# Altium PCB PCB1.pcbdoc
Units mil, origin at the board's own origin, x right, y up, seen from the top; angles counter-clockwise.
Board outline 6799.22 x 4460.63 mil, 2 copper layers (Top Layer, Bottom Layer); 35 components, 22 nets, 137 pads, 97 vias.
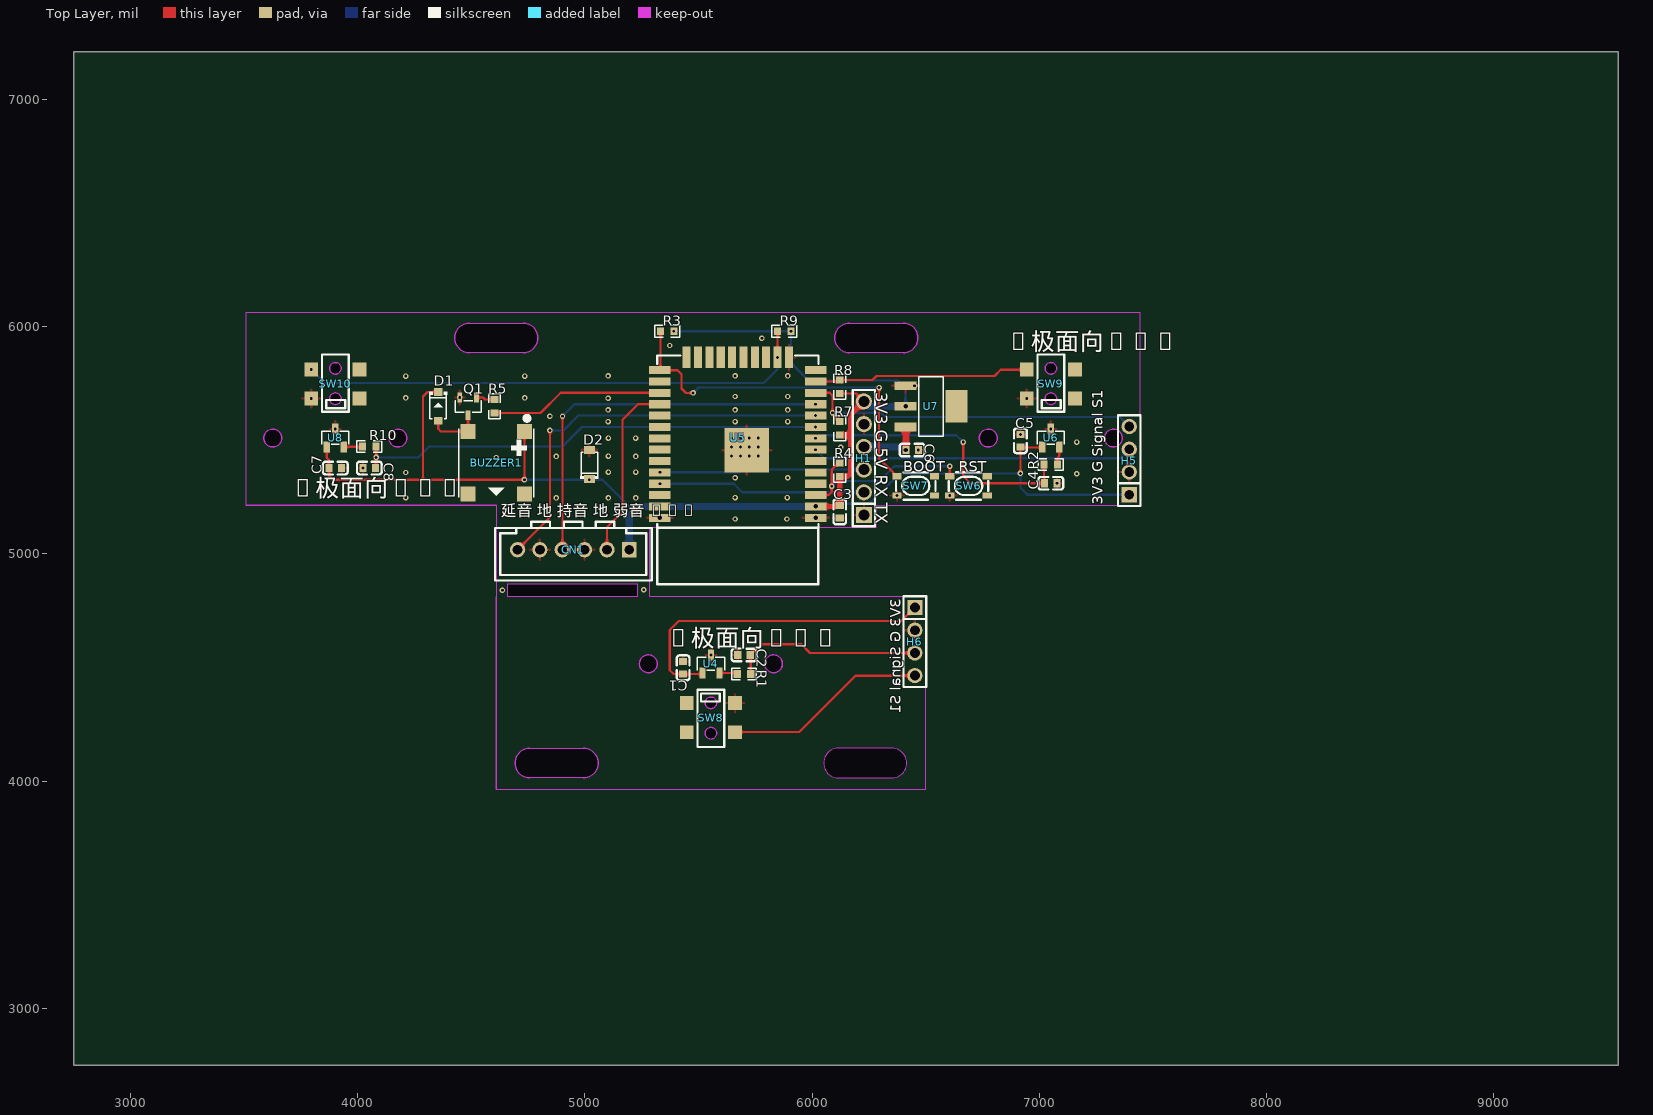
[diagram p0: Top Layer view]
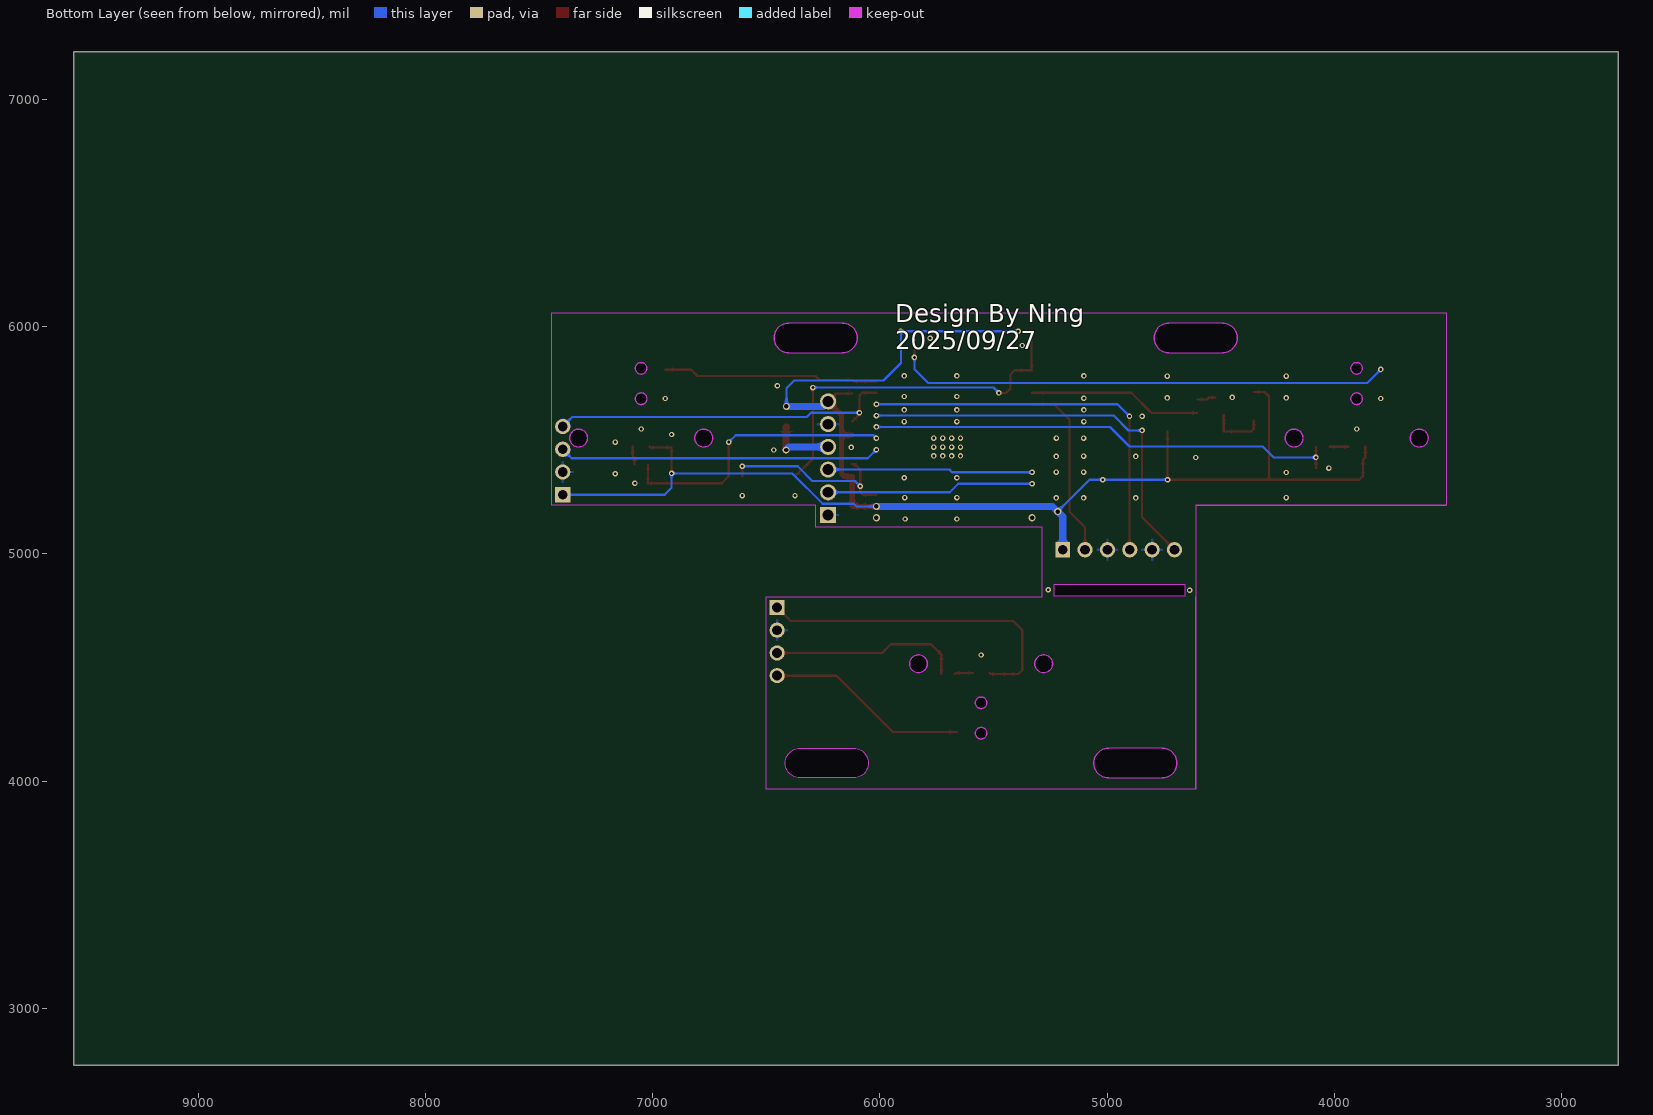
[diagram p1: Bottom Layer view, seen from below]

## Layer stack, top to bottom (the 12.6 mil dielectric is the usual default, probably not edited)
Top Layer: signal copper (thickness not stored)
Dielectric: dielectric 12.6, FR-4, Dk 4.8
Bottom Layer: signal copper (thickness not stored)

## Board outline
9549.22,2750 2750,2750 2750,7210.63 9549.22,7210.63
cut-out: 3665.35,5509.85 cw(c3625.98,5509.85) 3586.61,5509.85 cw(c3625.98,5509.85)
cut-out: 7366.14,5509.85 cw(c7326.77,5509.85) 7287.4,5509.85 cw(c7326.77,5509.85)
cut-out: 4216.54,5509.85 cw(c4177.17,5509.85) 4137.8,5509.85 cw(c4177.17,5509.85)
cut-out: 6814.96,5509.85 cw(c6775.59,5509.85) 6736.22,5509.85 cw(c6775.59,5509.85)
cut-out: 5318.9,4516.26 cw(c5279.53,4516.26) 5240.16,4516.26 cw(c5279.53,4516.26)
cut-out: 5870.08,4516.26 cw(c5830.71,4516.26) 5791.34,4516.26 cw(c5830.71,4516.26)
cut-out: 4492.13,5885.83 cw(c4492.13,5950.79) 4492.13,6015.75 4728.35,6015.75 cw(c4728.35,5950.79) 4728.35,5885.83
cut-out: 6165.35,5885.83 cw(c6165.35,5950.79) 6165.35,6015.75 6401.57,6015.75 cw(c6401.57,5950.79) 6401.57,5885.83
cut-out: 4757.6,4144.22 4993.82,4144.22 cw(c4993.82,4079.26) 4993.82,4014.3 4757.6,4014.3 cw(c4757.6,4079.26)
cut-out: 6352.09,4144.22 6115.87,4144.22 ccw(c6115.87,4079.26) 6115.87,4014.3 6352.09,4014.3 ccw(c6352.09,4079.26)
cut-out: 5233.82,4866.15 4659.53,4866.15 4659.53,4813 4659.48,4813 5233.82,4813

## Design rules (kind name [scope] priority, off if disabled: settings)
BoardOutlineClearance copperThickness1oz [All] p0: genericclearance=10 ignorepadtopadclearanceinfootprint=FALSE except(0: Arc-SplitContinuation Track-SplitContinuation SMDPad-SplitContinuation THPad-SplitContinuation Via-SplitContinuation Fill-SplitContinuation Poly-SplitContinuation Region-SplitContinuation Text-SplitContinuation; 6: Track-CutoutEdge SMDPad-CutoutEdge THPad-CutoutEdge Via-CutoutEdge Region-CutoutEdge; 11.8: Track-OutlineEdge SMDPad-OutlineEdge THPad-OutlineEdge Via-OutlineEdge Fill-OutlineEdge Region-OutlineEdge Poly-OutlineEdge Text-OutlineEdge Fill-CutoutEdge)
BoardOutlineClearance copperThickness2oz [All] p0: genericclearance=10 ignorepadtopadclearanceinfootprint=FALSE except(0: Arc-SplitContinuation Track-SplitContinuation SMDPad-SplitContinuation THPad-SplitContinuation Via-SplitContinuation Fill-SplitContinuation Poly-SplitContinuation Region-SplitContinuation Text-SplitContinuation; 6: Track-CutoutEdge SMDPad-CutoutEdge THPad-CutoutEdge Via-CutoutEdge Region-CutoutEdge; 11.8: Track-OutlineEdge SMDPad-OutlineEdge THPad-OutlineEdge Via-OutlineEdge Fill-OutlineEdge Region-OutlineEdge Poly-OutlineEdge Text-OutlineEdge Fill-CutoutEdge)
Clearance copperThickness1oz [(InNet('3V3') OR InNet('$1N2451') OR InNet('GND') OR InNet('SIGNAL1') OR InNet('5V') OR InNet('$1N2441') OR InNet('$1N652') OR InNet('$1N2297') OR InNet('IO0') OR InNet('EN') OR InNet('SPEAKER') OR InNet('OUT3') OR InNet('S1') OR InNet('S2') OR InNet('S3') OR InNet('SIGNAL2') OR InNet('DOUT1') OR InNet('DOUT2') OR InNet('RXD') OR InNet('TXD') OR InNet('SIGNAL3') OR InNet('$1N5432'))] p1: gap=7 ignorepadtopadclearanceinfootprint=FALSE except(4: Track-Track; 6: Track-SMDPad SMDPad-SMDPad Track-THPad SMDPad-THPad THPad-THPad Track-Via SMDPad-Via THPad-Via Via-Via SMDPad-Fill THPad-Fill Via-Fill Fill-Fill Track-Region SMDPad-Region THPad-Region Via-Region Region-Region Track-Poly SMDPad-Poly THPad-Poly Via-Poly Fill-Poly Region-Poly Poly-Poly Track-Text SMDPad-Text THPad-Text Via-Text Fill-Text Region-Text Poly-Text Text-Text; 6.9: Track-Hole SMDPad-Hole THPad-Hole Via-Hole Fill-Hole Region-Hole Poly-Hole Text-Hole Sheet-Hole; 11.8: Track-Fill Fill-Region Track-Sheet SMDPad-Sheet THPad-Sheet Via-Sheet Fill-Sheet Region-Sheet Poly-Sheet Text-Sheet)
Clearance copperThickness2oz [All] p1: gap=7 ignorepadtopadclearanceinfootprint=FALSE except(6: Track-SMDPad SMDPad-SMDPad Track-THPad SMDPad-THPad THPad-THPad Track-Via SMDPad-Via THPad-Via Via-Via SMDPad-Fill THPad-Fill Via-Fill Fill-Fill Track-Region SMDPad-Region THPad-Region Via-Region Region-Region Track-Poly SMDPad-Poly THPad-Poly Via-Poly Fill-Poly Region-Poly Poly-Poly Track-Text SMDPad-Text THPad-Text Via-Text Fill-Text Region-Text Poly-Text Text-Text; 6.9: Track-Hole SMDPad-Hole THPad-Hole Via-Hole Fill-Hole Region-Hole Poly-Hole Text-Hole Sheet-Hole; 8: Track-Track; 11.8: Track-Fill Fill-Region Track-Sheet SMDPad-Sheet THPad-Sheet Via-Sheet Fill-Sheet Region-Sheet Poly-Sheet Text-Sheet)
DiffPairsRouting differentialPair [All] p1: maxuncoupledlength=10 minlimit=6 maxlimit=6 mostfreqgap=6 toplayer_minwidth=5 toplayer_prefwidth=10 toplayer_maxwidth=100 bottomlayer_minwidth=5 bottomlayer_prefwidth=10 bottomlayer_maxwidth=100
PasteMaskExpansion pasteMaskExpansion [All] p1: expansion=0
PlaneConnect innerPlane [All] p1: planeconnectstyle=Relief reliefexpansion=20 reliefentries=4 reliefconductorwidth=10 reliefairgap=10
PolygonConnect copperRegion [All] p1: connectstyle=Relief reliefentries=4 reliefconductorwidth=10 polygonreliefangle="90 Angle" airgapwidth=10
RoutingVias viaSize [All] p1: viastyle="Through Hole" holewidth=12.0078 minholewidth=11.811 maxholewidth=248.0314 width=24.0158 minwidth=19.685 maxwidth=393.7008
SolderMaskExpansion solderMaskExpansion [All] p1: useseparateexpansions=TRUE expansion=2 expansionbottom=2
Width copperThickness1oz [All] p1: maxlimit=100 minlimit=5 preferedwidth=10
Width copperThickness2oz [All] p1: maxlimit=100 minlimit=8 preferedwidth=10

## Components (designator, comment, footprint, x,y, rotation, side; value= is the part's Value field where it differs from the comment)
BUZZER1 "MLT-7525" BUZ-SMD_4P-L7.5-W7.5-P7.59-TL 4610.24,5401.58 r270 top locked
C1 "CC0603KRX7R9BB103" C0603 5432.8,4498.55 r90 top
C2 "CC0603JRNPO9BN152" C0603 5700.79,4555.12 r180 top locked
C3 "CL10A106MA8NRNC" C0603 6122.05,5185.04 r270 top
C4 "CC0603JRNPO9BN152" C0603 7051.18,5311.03 r0 top
C5 "CC0603KRX7R9BB103" C0603 6917.32,5498.03 r90 top
C6 "CL10A106MA8NRNC" C0603 6440.66,5457.32 r180 top
C7 "CC0603KRX7R9BB103" C0603 3901.57,5377.96 r0 top
C8 "CC0603JRNPO9BN152" C0603 4051.28,5377.96 r180 top
CN1 "HC-XHB-6A" CONN-TH_6P-P2.50_HCTL_HC-XHB-6A 4949.54,5018.22 r180 top locked
D1 "1N4148W_C7420318" SOD-123_L2.7-W1.6-LS3.7-FD 4354.33,5649.61 r90 top locked
D2 "BZT52C3V3_C19077396" SOD-123_L2.7-W1.6-LS3.7-RD 5019.68,5393.7 r90 top locked
H1 "2.54-1x6P直针" HDR-TH_6P-P2.54-V-M-1 6228.35,5421.26 r90 top locked
H5 "PZ254V-11-04P" HDR-TH_4P-P2.54-V-M 7396.46,5410.63 r90 top locked
H6 "PZ254V-11-04P" HDR-TH_4P-P2.54-V-M 6452.76,4614.18 r270 top locked
Q1 "S8050_C20069125" SOT-23-3_L2.9-W1.3-P1.90-LS2.3-BR 4486.22,5649.61 r90 top locked
R1 "0603WAF1002T5E" R0603 5700.51,4470.99 r180 top locked
R2 "0603WAF1002T5E" R0603 7051.18,5393.7 r0 top
R3 "0603WAF1002T5E" R0603 5362.2,5980.32 r0 top locked
R4 "0603WAF1002T5E" R0603 6122.05,5370.23 r270 top
R5 "0603WAF1800T5E" R0603 4602.36,5649.61 r90 top locked
R7 "0603WAF1002T5E" R0603 6122.05,5553.23 r90 top
R8 "0603WAF1002T5E" R0603 6122.05,5736.22 r90 top
R9 "0603WAF1002T5E" R0603 5877.95,5980.32 r180 top locked
R10 "0603WAF1002T5E" R0603 4051.18,5472.44 r180 top locked
SW6 "SKRPACE010" KEY-SMD_4P-L4.2-W3.2-P2.20-LS4.6 6688.98,5299.22 r0 top
SW7 "SKRPACE010" KEY-SMD_4P-L4.2-W3.2-P2.20-LS4.6 6456.69,5299.22 r0 top
SW8 "TM-T07A-6" SW-SMD_TM-T07A-4 5554.84,4279.53 r90 top locked
SW9 "TM-T07A-6" SW-SMD_TM-T07A-4 7051.18,5748.04 r270 top locked
SW10 "TM-T07A-6" SW-SMD_TM-T07A-4 3901.57,5748.04 r270 top locked
U4 "DRV5053VAQDBZR" SOT-23-3_L2.9-W1.3-P1.90-LS2.4-BR 5554.84,4515.57 r270 top locked
U5 "ESP32-WROOM-32-N8" WIFIM-SMD_39P-L25.5-W18.0-P1.27 5673.23,5511.81 r180 top locked
U6 "DRV5053VAQDBZR" SOT-23-3_L2.9-W1.3-P1.90-LS2.4-BR 7051.18,5510.54 r270 top locked
U7 "AMS1117-3.3_C347222" SOT-223-4_L6.5-W3.5-P2.30-LS7.0-BR 6523.62,5649.61 r180 top
U8 "DRV5053VAQDBZR" SOT-23-3_L2.9-W1.3-P1.90-LS2.4-BR 3901.57,5510.54 r270 top locked

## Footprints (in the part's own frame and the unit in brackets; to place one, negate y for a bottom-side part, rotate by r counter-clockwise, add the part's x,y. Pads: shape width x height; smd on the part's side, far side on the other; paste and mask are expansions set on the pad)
BUZ-SMD_4P-L7.5-W7.5-P7.59-TL [mm]
  rect 1.681x1.68 smd: 1(-3.497,3.15) 2(-3.497,-3.15) 3(3.497,-3.15) 4(3.497,3.15)
  silkscreen extent -5.2,-4.19 3.84,4.19
C0603 [mm]
  rect 0.8x0.9 smd: 1(-0.7,0) 2(0.7,0)
  silkscreen extent -1.39,-0.71 1.39,0.71
CONN-TH_6P-P2.50_HCTL_HC-XHB-6A [mm]
  rect 1.6x1.7 hole 1.1: 1(-6.25,0)
  round 1.7 hole 1.1: 2(-3.75,0) 3(-1.25,0) 4(1.25,0) 5(3.75,0) 6(6.25,0)
  silkscreen extent -8.75,-3.14 8.76,3.44
HDR-TH_4P-P2.54-V-M [mm]
  rect 1.7x1.7 hole 1.1: 1(-3.81,0)
  round 1.7 hole 1.1: 2(-1.27,0) 3(1.27,0) 4(3.81,0)
  silkscreen extent -5.08,-1.27 5.08,1.27
HDR-TH_6P-P2.54-V-M-1 [mm]
  rect 1.8x1.8 hole 1.2: 1(-6.35,0)
  round 1.8 hole 1.2: 2(-3.81,0) 3(-1.27,0) 4(1.27,0) 5(3.81,0) 6(6.35,0)
  silkscreen extent -7.62,-1.25 7.62,1.25
KEY-SMD_4P-L4.2-W3.2-P2.20-LS4.6 [mm]
  rect 1.05x0.7 smd: 1(-2.1,1.075) 2(2.1,1.075) 3(-2.1,-1.075) 4(2.1,-1.075)
  silkscreen extent -2.2,-1.55 2.2,1.52
R0603 [mil]
  rect 31.75x34.02 smd: 1(-29.66,0) 2(29.66,0)
  silkscreen extent -55,-26 55,26
SOD-123_L2.7-W1.6-LS3.7-FD [mm]
  rect 0.88x0.96 smd: 1(-1.61,0) 2(1.61,0)
  silkscreen extent -1.38,-1 1.6,1
SOD-123_L2.7-W1.6-LS3.7-RD [mm]
  rect 0.91x1.22 smd: 1(-1.635,0) 2(1.635,0)
  silkscreen extent -1.6,-1 1.38,1
SOT-23-3_L2.9-W1.3-P1.90-LS2.3-BR [mm]
  rect 1.07x0.532 smd: 1(0.99,-0.95) 2(0.99,0.95) 3(-0.99,0)
  silkscreen extent -0.66,-1.45 0.64,1.45
SOT-23-3_L2.9-W1.3-P1.90-LS2.4-BR [mm]
  rect 1.25x0.7 smd: 1(1,-0.95) 2(1,0.95) 3(-1,0)
  silkscreen extent -0.73,-1.53 0.73,1.53
SOT-223-4_L6.5-W3.5-P2.30-LS7.0-BR [mm]
  rect 2.47x0.98 smd: 1(2.835,-2.3) 2(2.835,0) 3(2.835,2.3)
  rect 2.47x3.6 smd: 4(-2.835,0)
  silkscreen extent -1.37,-3.33 1.37,3.33
SW-SMD_TM-T07A-4 [mil]
  rect 60x60 smd: 1(-63.97,-106.3) 2(63.98,-106.3) 3(63.98,106.3) 4(-63.97,106.3)
  Board Outline Layer circle w1: c64.96,0 r25.59
  Board Outline Layer circle w1: c-68.9,0.2 r25.59
  Board Outline Layer region: 64.96,-25.59 53.86,-23.06 44.95,-15.96 40.01,-5.69 40.01,5.69 44.95,15.96 53.86,23.06 64.96,25.59 64.96,25.59 76.06,23.06 84.97,15.96 89.91,5.69 89.91,-5.69 84.97,-15.96 76.06,-23.06 64.96,-25.59
  Board Outline Layer region: -68.9,-25.39 -80,-22.86 -88.91,-15.76 -93.85,-5.5 -93.85,5.89 -88.91,16.15 -80,23.25 -68.9,25.79 -68.9,25.79 -57.79,23.25 -48.89,16.15 -43.95,5.89 -43.95,-5.5 -48.89,-15.76 -57.79,-22.86 -68.9,-25.39
  Multi-Layer board cut-out: 64.96,-25.59 53.86,-23.06 44.95,-15.96 40.01,-5.69 40.01,5.69 44.95,15.96 53.86,23.06 64.96,25.59 64.96,25.59 76.06,23.06 84.97,15.96 89.91,5.69 89.91,-5.69 84.97,-15.96 76.06,-23.06 64.96,-25.59
  Multi-Layer board cut-out: -68.9,-25.39 -80,-22.86 -88.91,-15.76 -93.85,-5.5 -93.85,5.89 -88.91,16.15 -80,23.25 -68.9,25.79 -68.9,25.79 -57.79,23.25 -48.89,16.15 -43.95,5.89 -43.95,-5.5 -48.89,-15.76 -57.79,-22.86 -68.9,-25.39
  silkscreen extent -130,-59 122,59
WIFIM-SMD_39P-L25.5-W18.0-P1.27 [mm]
  rect 2.4x0.9 smd: 1(-8.7,8.965) 2(-8.7,7.695) 3(-8.7,6.425) 4(-8.7,5.155) 5(-8.7,3.885) 6(-8.7,2.615) 7(-8.7,1.345) 8(-8.7,0.075) 9(-8.7,-1.195) 10(-8.7,-2.465) 11(-8.7,-3.735) 12(-8.7,-5.005) 13(-8.7,-6.275) 14(-8.7,-7.545) 25(8.7,-7.545) 26(8.7,-6.275) 27(8.7,-5.005) 28(8.7,-3.735) 29(8.7,-2.465) 30(8.7,-1.195) 31(8.7,0.075) 32(8.7,1.345) 33(8.7,2.615) 34(8.7,3.885) 35(8.7,5.155) 36(8.7,6.425) 37(8.7,7.695) 38(8.7,8.965)
  rect 0.9x2.4 smd: 15(-5.715,-8.965) 16(-4.445,-8.965) 17(-3.175,-8.965) 18(-1.905,-8.965) 19(-0.635,-8.965) 20(0.635,-8.965) 21(1.905,-8.965) 22(3.175,-8.965) 23(4.445,-8.965) 24(5.715,-8.965)
  rect 5x5 smd: 39(-1.017,1.422)
  silkscreen extent -9.02,-9.17 9.02,16.39

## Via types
v1: diameter 24.02, hole 12.01, Top Layer to Bottom Layer, 91 vias
v2: diameter 31.5, hole 19.68, Top Layer to Bottom Layer, 6 vias

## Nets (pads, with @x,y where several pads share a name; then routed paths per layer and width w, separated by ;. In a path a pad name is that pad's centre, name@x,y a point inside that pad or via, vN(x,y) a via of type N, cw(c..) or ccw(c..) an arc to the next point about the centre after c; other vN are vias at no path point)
3V3: BUZZER1.1 C1.1 C3.1 C5.1 C7.1 CN1.1 D1.2 D2.1 H1.6 H5.1 H6.1 R3.2 R4.2 R7.1 R8.1 R9.1 U4.1 U5.2 U6.1 U7.2 U8.1 | length 8637.7
  Top Layer w10: U8.1 3864.17,5423.23 3874.01,5413.39 C7.1 3874.01,5342.52 3889.76,5326.78 4286.9,5326.78 ; D1.2 4307.48,5713 4287.4,5692.92 4287.4,5327.27 4286.9,5326.78 ; BUZZER1.1 v1(4734.25,5326.78) 4286.9,5326.78 ; U4.1 5512.23,4470.99 C1.1 5391.22,4470.99 5374.02,4488.19 5374.02,4665.36 5413.39,4704.73 6393.31,4704.73 H6.1 ; R8.1 6193.05,5706.56 H1.6 ; v1(6917.32,5354.33) C5.1@6917.32,5468.51 ; C5.1 C5.1@6917.32,5468.51 ; U6.1 7011.12,5468.51 C5.1@6917.32,5468.51
  Top Layer w23.62: v2(6015.74,5208.86) 6118.3,5208.86 C3.1 R4.2 6155.53,5340.57 6169.29,5354.33 6169.29,5525.61 ; R7.1 6167.25,5523.57 6169.29,5525.61 ; H1.6 6169.29,5612.21 6169.29,5525.61
  Bottom Layer w10: v1@4732.28,5326.78 v1(5019.46,5326.78) 5077.27,5326.78 v2(5217.77,5186.28) ; v1@5393.7,5980.32 v1(5907.61,5980.32) 5907.61,5840.42 5984.25,5763.78 6377.95,5763.78 6412.01,5729.72 v2(6412.01,5649.61) ; v2(6015.74,5208.86) 6102.56,5208.86 6114.17,5220.48 6251.97,5220.48 6385.83,5354.33 v1(6917.32,5354.33) 6917.32,5291.34 6948.03,5260.63 H5.1
  Bottom Layer w31.5: CN1.1 5195.61,5164.12 v2(5217.77,5186.28) 5240.16,5208.67 v2@6015.74,5208.67 ; H1.6 6250,5649.61 v2(6412.01,5649.61)
  other v1: 5391.86,5980.32
5V: C6.2 H1.4 U7.3 | length 292.7
  Top Layer w31.5: U7.3 6413.1,5557.97 v2(6413.1,5457.32)
  Bottom Layer w31.5: H1.4 6399.16,5471.26 v2(6413.1,5457.32)
$1N652: R1.2 U4.2 | length 80.8
  Top Layer w10: U4.2 5665.64,4476.2 R1.2
$1N2297: R2.2 U6.2 | length 80.7
  Top Layer w10: R2.2 7080.84,5423.36 7088.58,5431.1 U6.2
$1N2441: Q1.1 R5.2 | length 82.6
  Top Layer w10: Q1.1 4551.57,5688.6 4560.89,5679.27 R5.2
$1N2451: BUZZER1.2 D1.1 Q1.3 | length 243.2
  Top Layer w10: D1.1 4354.33,5551.19 4366.24,5539.27 BUZZER1.2 Q1.3
$1N5432: R10.2 U8.2 | length 83.1
  Top Layer w10: U8.2 4020.24,5471.17 R10.2
DOUT1: CN1.6 U5.10 | length 1780.8
  Top Layer w10: CN1.6 4846.46,5161.2 v1(4846.46,5543.31)
  Bottom Layer w10: v1(4846.46,5543.31) 4905.51,5543.31 4971.06,5608.86 v1(6015.74,5608.86)
DOUT2: CN1.4 U5.11 | length 1724.5
  Top Layer w10: CN1.4 4901.57,5019.46 v1(4901.57,5606.3)
  Bottom Layer w10: v1(4901.57,5606.3) 4954.13,5658.86 v1(6015.74,5658.86)
EN: R4.1 SW6.1 U5.3 | length 821.4
  Top Layer w10: U5.3 6073.82,5258.86 6086.61,5271.66 v1(6086.61,5297.41) 6086.61,5371.02 6110.24,5394.64 R4.1@6122.05,5394.64 ; SW6.1 v1(6606.3,5385.83)
  Bottom Layer w10: v1(6086.61,5297.41) 6110.47,5321.26 6297.64,5321.26 6362.21,5385.83 v1(6606.3,5385.83)
GND: C1.2 C2.2 C3.2 C4.2 C5.2 C6.1 C7.2 C8.2 CN1.3 CN1.5 D2.2 H1.1 H1.5 H5.2 H6.2 Q1.2 SW6.3 SW7.3 SW8.2 SW9.2 SW10.2 U4.3 U5.1 U5.15 U5.38 U5.39 U6.3 U7.1 U8.3
  other v1: 5554.84,4554.94 4637.4,4839.57 5259.84,4842.52 5661.42,5153.55 5889.76,5153.55 4874.02,5246.18 5103.82,5246.18 5224.41,5246.18 4211.81,5248.04 5661.42,5248.04 5891.56,5248.04 6374.01,5256.9 6606.3,5256.9 7078.74,5311.03 5661.42,5334.65 5893.69,5334.65 7165.36,5352.69 4211.81,5358.32 5103.82,5360.13 5224.41,5360.13 4023.72,5377.96 4610.24,5424.34 4874.02,5429.14 5224.41,5429.14 5103.82,5430.67 5645.56,5431.11 5684.93,5431.11 5724.3,5431.11 5763.67,5431.11 6468.22,5457.32 6125.98,5468.51 5645.56,5470.48 5684.93,5470.48 5724.3,5470.48 5763.67,5470.48 7165.36,5492.13 5103.82,5509.85 5223.2,5509.85 5645.56,5509.85 5684.93,5509.85 5724.3,5509.85 5763.67,5509.85 6917.32,5525.59 3901.57,5549.91 7051.18,5549.91 5102.36,5582.6 5661.42,5582.68 5893.69,5582.68 4846.46,5606.3 5102.36,5633.86 5661.42,5633.86 5892.79,5633.86 3795.27,5684.06 6944.88,5684.06 5102.36,5685.04 4211.81,5686.62 4735.39,5686.6 4448.82,5688.6 5661.42,5692.92 5892.79,5692.92 6451.38,5740.16 4211.81,5782.91 4735.39,5782.91 5102.36,5783.47 5661.42,5783.47 5892.79,5783.47 5374.02,5917.33 5779.53,5948.82
  other v2: 5330.71,5158.86 6015.74,5158.86
IO0: R3.1 SW7.1 U5.25 | length 1648.3
  Top Layer w10: R3.1 5332.54,5810.69 U5.25 5407.68,5808.86 5425.2,5791.34 5425.2,5728.35 5444.88,5708.67 v1(5476.38,5708.67) ; v1(6295.28,5732.29) 6295.28,5420.27 SW7.1
  Bottom Layer w10: v1(5476.38,5708.67) 5500,5732.29 v1(6295.28,5732.29)
OUT3: CN1.2 U5.28 | length 794.2
  Top Layer w10: CN1.2 5097.18,5116.87 5165.35,5185.04 5165.35,5590.56 5233.66,5658.86 U5.28
RXD: H1.3 U5.34 | length 902.8
  Bottom Layer w10: v1(5330.71,5358.86) 5681.69,5358.86 5694.09,5371.26 H1.3
S1: H5.4 H6.4 R7.2 SW8.1 U5.12 | length 2432.5
  Top Layer w10: SW8.1 5943.9,4215.56 6192.52,4464.18 H6.4 ; U5.12 6078.55,5708.86 6090.55,5696.85 v1(6090.55,5621.51) 6090.55,5614.38 R7.2
  Bottom Layer w10: v1(6090.55,5621.51) 6303.69,5621.51 6322.84,5602.37 7354.73,5602.37 H5.4
S2: R8.2 SW9.1 U5.13 | length 951.2
  Top Layer w10: U5.13 6115.02,5758.86 R8.2 6265.88,5765.88 6283.47,5783.47 6803.15,5783.47 6830.71,5811.03 6943.9,5811.03 SW9.1
S3: R9.2 SW10.1 U5.16 | length 2270.5
  Top Layer w10: U5.16@5848.29,5864.84 R9.2
  Bottom Layer w10: v1(3795.27,5812.01) 3855.31,5751.97 5787.4,5751.97 5848.23,5812.8 v1(5848.23,5864.77)
SIGNAL1: C2.1 H5.3 H6.3 R1.1 U5.7 | length 2257.3
  Top Layer w10: R1.1 5730.17,4553.3 C2.1 5775.59,4602.37 5952.76,4602.37 5990.95,4564.18 H6.3
  Bottom Layer w10: v1(6015.74,5458.86) 6053.34,5421.26 7357.09,5421.26 H5.3
SIGNAL2: C4.1 R2.1 U5.8 | length 1272.6
  Top Layer w10: v1(6665.35,5492.13) 6665.35,5342.52 6696.85,5311.03 C4.1 7021.52,5313.13 R2.1
  Bottom Layer w10: v1(6015.74,5508.86) 6029.72,5522.84 6634.65,5522.84 v1(6665.35,5492.13)
SIGNAL3: C8.1 R10.1 U5.9 | length 2085.8
  Top Layer w10: C8.1 4080.84,5379.96 v1(4080.84,5424.65) R10.1
  Bottom Layer w10: v1(4080.84,5424.65) 4267.16,5424.65 4314.96,5472.44 4901.57,5472.44 4987.99,5558.86 v1(6015.74,5558.86)
SPEAKER: R5.1 U5.27 | length 765.2
  Top Layer w10: R5.1 4804.99,5619.95 4893.89,5708.86 U5.27
TXD: H1.2 U5.35 | length 913.2
  Bottom Layer w10: v1(5330.71,5308.86) 5655.71,5308.86 5693.31,5271.26 H1.2
pads on no net: BUZZER1.3 BUZZER1.4 SW6.2 SW6.4 SW7.2 SW7.4 SW8.3 SW8.4 SW9.3 SW9.4 SW10.3 SW10.4 U5.4 U5.5 U5.6 U5.14 U5.17 U5.18 U5.19 U5.20 U5.21 U5.22 U5.23 U5.24 U5.26 U5.29 U5.30 U5.31 U5.32 U5.33 U5.36 U5.37 U7.4

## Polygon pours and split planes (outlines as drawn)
GND on Top Layer (solid, remove dead copper, pour order 0): 3000,6960.63 9299.22,6960.63 9299.22,3000 3000,3000
GND on Bottom Layer (solid, remove dead copper, pour order 2): 3055.12,6913.39 7937.01,6913.39 7937.01,3047.25 3055.12,3047.25

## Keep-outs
Board Outline Layer:
  circle w1: c3625.98,5509.85 r39.37
  region: 3665.35,5509.85 cw(c3625.98,5509.85) 3586.61,5509.85 cw(c3625.98,5509.85)
  circle w1: c7326.77,5509.85 r39.37
  region: 7366.14,5509.85 cw(c7326.77,5509.85) 7287.4,5509.85 cw(c7326.77,5509.85)
  circle w1: c4177.17,5509.85 r39.37
  region: 4216.54,5509.85 cw(c4177.17,5509.85) 4137.8,5509.85 cw(c4177.17,5509.85)
  circle w1: c6775.59,5509.85 r39.37
  region: 6814.96,5509.85 cw(c6775.59,5509.85) 6736.22,5509.85 cw(c6775.59,5509.85)
  circle w1: c5279.53,4516.26 r39.37
  region: 5318.9,4516.26 cw(c5279.53,4516.26) 5240.16,4516.26 cw(c5279.53,4516.26)
  circle w1: c5830.71,4516.26 r39.37
  region: 5870.08,4516.26 cw(c5830.71,4516.26) 5791.34,4516.26 cw(c5830.71,4516.26)
  region: 4492.13,5885.83 cw(c4492.13,5950.79) 4492.13,6015.75 4728.35,6015.75 cw(c4728.35,5950.79) 4728.35,5885.83
  region: 6165.35,5885.83 cw(c6165.35,5950.79) 6165.35,6015.75 6401.57,6015.75 cw(c6401.57,5950.79) 6401.57,5885.83
  region: 4757.6,4144.22 4993.82,4144.22 cw(c4993.82,4079.26) 4993.82,4014.3 4757.6,4014.3 cw(c4757.6,4079.26)
  region: 6352.09,4144.22 6115.87,4144.22 ccw(c6115.87,4079.26) 6115.87,4014.3 6352.09,4014.3 ccw(c6352.09,4079.26)
  region: 5233.82,4866.15 4659.53,4866.15 4659.53,4813 4659.48,4813 5233.82,4813
  lines w1: 4492.13,5885.83 cw(c4492.13,5950.79) 4492.13,6015.75 4728.35,6015.75 cw(c4728.35,5950.79) 4728.35,5885.83 4492.13,5885.83 ; 4659.48,4813 4659.53,4813 4659.53,4866.15 5233.82,4866.15 5233.82,4813 4659.48,4813 ; 4757.6,4014.3 4993.82,4014.3 ccw(c4993.82,4079.26) 4993.82,4144.22 4757.6,4144.22 ccw(c4757.6,4079.26) 4757.6,4014.3 ; 6115.87,4014.3 cw(c6115.87,4079.26) 6115.87,4144.22 6352.09,4144.22 cw(c6352.09,4079.26) 6352.09,4014.3 6115.87,4014.3 ; 6165.35,5885.83 cw(c6165.35,5950.79) 6165.35,6015.75 6401.57,6015.75 cw(c6401.57,5950.79) 6401.57,5885.83 6165.35,5885.83
  lines w3.94: 4610.19,4806.78 4610.2,5214.57 ; 3507.87,5214.57 3507.87,6061.03 7444.88,6061.03 7444.88,5214.57 7444.86,5214.57 6283.47,5214.57 6283.47,5118.11 5286.33,5118.11 5286.33,4813.14 5285.88,4811.54 6499.72,4811.54 6499.72,3965.08 4610.2,3965.08 ; 3507.87,5214.57 4610.2,5214.57 ; 3507.87,5214.57 4610.2,5214.57 ; 3507.87,5214.57 4610.2,5214.57 ; 4610.2,3965.08 4610.2,4811.54 ; 4610.2,3965.08 4610.2,4811.54 ; 4610.2,3965.08 4610.2,4811.54

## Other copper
Top Layer:
  region net 3V3: 4739.25,5501.18 4729.25,5501.18 ccw(c4724.25,5501.18) 4724.25,5506.18 4744.25,5506.18 ccw(c4744.25,5501.18)
  region net $1N2451: 4448.15,5534.27 4448.15,5544.27 ccw(c4448.15,5549.27) 4453.15,5549.27 4453.15,5529.27 ccw(c4448.15,5529.27)
  region net $1N2451: 4481.22,5577.36 4491.22,5577.36 ccw(c4496.22,5577.36) 4496.22,5572.36 4476.22,5572.36 ccw(c4476.22,5577.36)
  region net SIGNAL1: 5738.99,4572.84 5744.1,4563.8 5744.1,4556.73 5731.92,4572.84
  region net SIGNAL1: 5735.17,4532.4 5725.17,4532.4 ccw(c5720.17,4532.4) 5720.17,4537.4 5740.17,4537.4 ccw(c5740.17,4532.4)
  region net SIGNAL2: 7002.87,5306.03 7002.87,5316.03 ccw(c7002.87,5321.03) 7007.87,5321.03 7007.87,5301.03 ccw(c7002.87,5301.03)
  region net SIGNAL2: 7016.52,5333.74 7026.52,5333.74 ccw(c7031.52,5333.74) 7031.52,5328.74 7011.52,5328.74 ccw(c7011.52,5333.74)
  region net $1N2451: 4359.33,5563.9 4349.33,5563.9 ccw(c4344.33,5563.9) 4344.33,5568.9 4364.33,5568.9 ccw(c4364.33,5563.9)
  region net 3V3: 4330.43,5708 4330.43,5718 ccw(c4330.43,5723) 4335.43,5723 4335.43,5703 ccw(c4330.43,5703)
  region net $1N2451: 4491.22,5584.56 4481.22,5584.56 ccw(c4476.22,5584.56) 4476.22,5589.56 4496.22,5589.56 ccw(c4496.22,5584.56)
  region net $1N2441: 4539.09,5693.6 4539.09,5683.6 ccw(c4539.09,5678.6) 4534.09,5678.6 4534.09,5698.6 ccw(c4539.09,5698.6)
  region net 3V3: 5498.66,4465.99 5498.66,4475.99 ccw(c5498.66,4480.99) 5503.66,4480.99 5503.66,4460.99 ccw(c5498.66,4460.99)
  region net $1N652: 5611.02,4481.2 5611.02,4471.2 ccw(c5611.02,4466.2) 5606.02,4466.2 5606.02,4486.2 ccw(c5611.02,4486.2)
  region net 3V3: 6074.8,5220.67 6074.8,5197.05 ccw(c6074.8,5182.28) 6062.99,5191.14 6062.99,5226.57 ccw(c6074.8,5235.43)
  region net EN: 6067.99,5263.86 6067.99,5253.86 ccw(c6067.99,5248.86) 6062.99,5248.86 6062.99,5268.86 ccw(c6067.99,5268.86)
  region net S1: 6067.99,5713.86 6067.99,5703.86 ccw(c6067.99,5698.86) 6062.99,5698.86 6062.99,5718.86 ccw(c6067.99,5718.86)
  region net S2: 6067.99,5763.86 6067.99,5753.86 ccw(c6067.99,5748.86) 6062.99,5748.86 6062.99,5768.86 ccw(c6067.99,5768.86)
  region net S3: 5843.29,5917.02 5853.29,5917.02 ccw(c5858.29,5917.02) 5858.29,5912.02 5838.29,5912.02 ccw(c5838.29,5917.02)
  region net IO0: 5382.96,5813.86 5382.96,5803.86 ccw(c5382.96,5798.86) 5377.96,5798.86 5377.96,5818.86 ccw(c5382.96,5818.86)
  region net IO0: 5327.54,5831.57 5337.54,5831.57 ccw(c5342.54,5831.57) 5342.54,5826.57 5322.54,5826.57 ccw(c5322.54,5831.57)
  region net SPEAKER: 5278.47,5703.86 5278.47,5713.86 ccw(c5278.47,5718.86) 5283.47,5718.86 5283.47,5698.86 ccw(c5278.47,5698.86)
  region net OUT3: 5278.47,5653.86 5278.47,5663.86 ccw(c5278.47,5668.86) 5283.47,5668.86 5283.47,5648.86 ccw(c5278.47,5648.86)
  region net 3V3: 6995,5463.51 6995,5473.51 ccw(c6995,5478.51) 7000,5478.51 7000,5458.51 ccw(c6995,5458.51)
  region net $1N2297: 7093.58,5441.56 7083.58,5441.56 ccw(c7078.58,5441.56) 7078.58,5446.56 7098.58,5446.56 ccw(c7098.58,5441.56)
  region net 5V: 6428.85,5524.02 6397.35,5524.02 ccw(c6381.6,5524.02) 6381.6,5539.77 6444.6,5539.77 ccw(c6444.6,5524.02)
  region net 3V3: 6190.7,5701.84 6197.77,5708.91 6199.86,5707 6201.82,5705.54 6203.69,5704.5 6205.47,5703.83 6207.21,5703.48 6208.92,5703.39 6210.64,5703.52 6212.39,5703.83 6220.2,5705.79 6222.48,5706.23 6224.96,5706.55 6227.64,5706.69 6230.57,5706.63 6192.98,5669.04 6192.92,5671.97 6193.07,5674.65 6193.38,5677.13 6193.82,5679.41 6195.78,5687.22 6196.09,5688.97 6196.22,5690.69 6196.13,5692.4 6195.78,5694.14 6195.11,5695.93 6194.07,5697.79 6192.62,5699.75
  region net 3V3: 6202.59,5628.8 6185.88,5645.5 6187.26,5647 6188.43,5648.52 6189.41,5650.06 6190.22,5651.64 6191.41,5654.89 6192.13,5658.28 6192.51,5661.82 6192.69,5665.52 6192.98,5673.48 6230.57,5635.9 6222.6,5635.61 6218.9,5635.43 6215.36,5635.05 6211.97,5634.33 6208.72,5633.14 6207.15,5632.33 6205.6,5631.34 6204.08,5630.17
  region net 3V3: 6092.52,5197.05 6092.52,5220.67 ccw(c6092.52,5233.59) 6104.33,5228.35 6104.33,5196.86 ccw(c6092.52,4833.39) 6092.52,5197.05
  region net 3V3: 6110.24,5240.16 6133.86,5240.16 ccw(c6148.63,5240.16) 6139.76,5228.35 6104.33,5228.35 ccw(c6095.48,5240.16)
  region net $1N652: 5649.98,4471.2 5649.98,4481.2 ccw(c5649.98,4486.2) 5654.98,4486.2 5654.98,4466.2 ccw(c5649.98,4466.2)
  region net SIGNAL1: 5725.17,4493 5735.17,4493 ccw(c5740.17,4493) 5740.17,4488 5720.17,4488 ccw(c5720.17,4493)
  region net $1N2297: 7075.84,5415.71 7085.84,5415.71 ccw(c7090.84,5415.71) 7090.84,5410.71 7070.84,5410.71 ccw(c7070.84,5415.71)
  region net SIGNAL2: 7026.52,5371.7 7016.52,5371.7 ccw(c7011.52,5371.7) 7011.52,5376.7 7031.52,5376.7 ccw(c7031.52,5371.7)
  region net IO0: 5337.54,5958.31 5327.54,5958.31 ccw(c5322.54,5958.31) 5322.54,5963.31 5342.54,5963.31 ccw(c5342.54,5958.31)
  region net 3V3: 6133.86,5312.88 6110.24,5312.88 ccw(c6094.22,5312.88) 6105.04,5324.69 6139.06,5324.69 ccw(c6149.88,5312.88) 6133.86,5312.88
  region net 3V3: 6150.87,5352.38 6150.87,5328.76 ccw(c6150.87,5309.57) 6139.06,5324.69 6139.06,5356.45 ccw(c6150.87,5371.57)
  region net EN: 6106.68,5384.01 6105.04,5396.52 6105.04,5400.05 6105.04,5403.59 6105.04,5396.52 6105.04,5400.05 6105.04,5403.59 6113.75,5384.01 6110.22,5384.01
  region net $1N2441: 4580.35,5674.27 4580.35,5684.27 ccw(c4580.35,5689.27) 4585.35,5689.27 4585.35,5669.27 ccw(c4580.35,5669.27)
  region net SPEAKER: 4624.37,5624.95 4624.37,5614.95 ccw(c4624.37,5609.95) 4619.37,5609.95 4619.37,5629.95 ccw(c4624.37,5629.95)
  region net S1: 6105.04,5592.82 6113.24,5598.76 6120.32,5598.76 6105.04,5585.75 6105.04,5589.29
  region net 3V3: 6150.87,5535.38 6150.87,5511.76 ccw(c6150.87,5492.56) 6139.06,5507.69 6139.06,5539.44 ccw(c6150.87,5554.57)
  region net S2: 6100.04,5753.86 6100.04,5763.86 ccw(c6100.04,5768.86) 6105.04,5768.86 6105.04,5750.01 ccw(c6100.04,5748.69)
  region net S2: 6144.06,5770.88 6144.06,5760.88 ccw(c6144.06,5755.88) 6139.06,5755.88 6139.06,5775.88 ccw(c6144.06,5775.88)
  region net 3V3: 6144.06,5711.56 6144.06,5701.56 ccw(c6144.06,5696.56) 6139.06,5696.56 6139.06,5716.56 ccw(c6144.06,5716.56)
  region net S3: 5853.29,5958.31 5843.29,5958.31 ccw(c5838.29,5958.31) 5838.29,5963.31 5858.29,5963.31 ccw(c5858.29,5958.31)
  region net SIGNAL3: 4075.84,5400.68 4085.84,5400.68 ccw(c4090.84,5400.68) 4090.84,5395.68 4070.84,5395.68 ccw(c4070.84,5400.68)
  region net OUT3: 5092.18,5063.78 5102.18,5063.78 5102.29,5061.14 5102.63,5058.88 5103.17,5056.95 5103.91,5055.31 5104.82,5053.91 5105.89,5052.69 5107.11,5051.62 5108.46,5050.64 5114.9,5046.68 5118.53,5044.01 5120.39,5042.33 5122.28,5040.35 5072.08,5040.35 5073.96,5042.33 5075.83,5044.01 5079.46,5046.68 5085.9,5050.64 5087.25,5051.62 5088.47,5052.69 5089.54,5053.91 5090.45,5055.31 5091.18,5056.95 5091.73,5058.88 5092.06,5061.14
  region net DOUT2: 4896.57,5064.7 4906.57,5062.83 4906.74,5061.35 4907.22,5059.84 4907.97,5058.3 4908.96,5056.74 4911.5,5053.59 4914.56,5050.46 4921.09,5044.51 4923.98,5041.82 4926.23,5039.4 4876.07,5041.27 4877.99,5043.15 4879.9,5044.77 4883.6,5047.39 4887.06,5049.5 4890.17,5051.45 4891.55,5052.47 4892.79,5053.59 4893.88,5054.84 4894.81,5056.28 4895.56,5057.93 4896.11,5059.86 4896.46,5062.1
  region net DOUT1: 4732.16,5053.97 4739.23,5046.9 4737.44,5044.95 4736.08,5043.11 4735.1,5041.37 4734.46,5039.69 4734.12,5038.05 4734.02,5036.44 4734.12,5034.82 4734.38,5033.17 4736.14,5025.82 4736.81,5021.36 4736.94,5018.85 4736.88,5016.12 4701.38,5051.62 4704.11,5051.68 4706.62,5051.55 4711.08,5050.88 4718.43,5049.12 4720.08,5048.86 4721.7,5048.76 4723.31,5048.86 4724.95,5049.2 4726.63,5049.84 4728.37,5050.82 4730.21,5052.18
  region net $1N5432: 4000.64,5466.17 4000.64,5476.17 ccw(c4000.64,5481.17) 4005.64,5481.17 4005.64,5461.17 ccw(c4000.64,5461.17)
  region net SIGNAL3: 4085.84,5450.44 4075.84,5450.44 ccw(c4070.84,5450.44) 4070.84,5455.44 4090.84,5455.44 ccw(c4090.84,5450.44)
  region net 3V3: 3869.17,5441.56 3859.17,5441.56 ccw(c3854.17,5441.56) 3854.17,5446.56 3874.17,5446.56 ccw(c3874.17,5441.56)
  region net $1N5432: 3957.75,5476.17 3957.75,5466.17 ccw(c3957.75,5461.17) 3952.75,5461.17 3952.75,5481.17 ccw(c3957.75,5481.17)
  region net EN: 6601.3,5360.32 6611.3,5360.32 ccw(c6616.3,5360.32) 6616.3,5355.32 6596.3,5355.32 ccw(c6596.3,5360.32)
  region net IO0: 6353.34,5355.13 6367.31,5355.32 6374.38,5355.32 6353.34,5348.06 6353.34,5351.6
  region net 3V3: 6426.36,4730.71 6419.29,4737.78 6419.29,4741.32 6419.29,4744.85 6419.29,4737.78 6419.29,4741.32 6419.29,4744.85 6433.43,4730.71 6429.9,4730.71
  region net SIGNAL1: 6407.2,4559.18 6407.2,4569.18 6409.84,4569.29 6412.1,4569.63 6414.02,4570.17 6415.66,4570.9 6417.07,4571.81 6418.28,4572.89 6419.35,4574.11 6420.33,4575.46 6424.29,4581.9 6426.97,4585.53 6428.65,4587.39 6430.62,4589.28 6430.62,4539.08 6428.65,4540.96 6426.97,4542.83 6424.29,4546.46 6420.33,4552.9 6419.35,4554.25 6418.28,4555.47 6417.07,4556.54 6415.66,4557.45 6414.02,4558.18 6412.1,4558.73 6409.84,4559.06
  region net S1: 6407.2,4459.18 6407.2,4469.18 6409.84,4469.29 6412.1,4469.63 6414.02,4470.17 6415.66,4470.9 6417.07,4471.81 6418.28,4472.89 6419.35,4474.11 6420.33,4475.46 6424.29,4481.9 6426.97,4485.53 6428.65,4487.39 6430.62,4489.28 6430.62,4439.08 6428.65,4440.96 6426.97,4442.83 6424.29,4446.46 6420.33,4452.9 6419.35,4454.25 6418.28,4455.47 6417.07,4456.54 6415.66,4457.45 6414.02,4458.18 6412.1,4458.73 6409.84,4459.06
  region net S1: 5696.14,4220.56 5696.14,4210.56 ccw(c5696.14,4205.56) 5691.14,4205.56 5691.14,4225.56 ccw(c5696.14,4225.56)
  region net S2: 6909.88,5806.03 6909.88,5816.03 ccw(c6909.88,5821.03) 6914.88,5821.03 6914.88,5801.03 ccw(c6909.88,5801.03)
  region net 3V3: 5455.51,4475.99 5455.51,4465.99 ccw(c5455.51,4460.99) 5450.51,4460.99 5450.51,4480.99 ccw(c5455.51,4480.99)
  region net 3V3: 5410.08,4465.99 5410.08,4475.99 ccw(c5410.08,4480.99) 5415.08,4480.99 5415.08,4460.99 ccw(c5410.08,4460.99)
  region net 3V3: 6922.32,5449.73 6912.32,5449.73 ccw(c6907.32,5449.73) 6907.32,5454.73 6927.32,5454.73 ccw(c6927.32,5449.73)
  region net 3V3: 6940.04,5473.51 6940.04,5463.51 ccw(c6940.04,5458.51) 6935.04,5458.51 6935.04,5478.51 ccw(c6940.04,5478.51)
  region net 3V3: 3879.01,5355.24 3869.01,5355.24 ccw(c3864.01,5355.24) 3864.01,5360.24 3884.01,5360.24 ccw(c3884.01,5355.24)
  region net 3V3: 3869.01,5400.67 3879.01,5400.67 ccw(c3884.01,5400.67) 3884.01,5395.67 3864.01,5395.67 ccw(c3864.01,5400.67)
  region net IO0: 6300.28,5715.94 6290.28,5715.94 6290.19,5717.08 6289.93,5718.21 6289.02,5720.43 6287.74,5722.5 6286.27,5724.35 6304.28,5724.35 6302.81,5722.5 6301.53,5720.43 6300.62,5718.21 6300.37,5717.08
  region net SIGNAL2: 6670.35,5475.78 6660.35,5475.78 6660.27,5476.92 6660.01,5478.05 6659.1,5480.27 6657.82,5482.34 6656.35,5484.19 6674.36,5484.19 6672.89,5482.34 6671.61,5480.27 6670.7,5478.05 6670.44,5476.92
  region net 3V3: 6034.64,5220.67 6034.64,5197.05 6031.16,5196.88 6027.84,5196.43 6024.77,5195.8 6022.02,5195.08 6017.79,5193.73 6015.74,5193.11 6015.74,5224.61 6017.79,5223.99 6022.02,5222.64 6024.77,5221.91 6027.84,5221.28 6031.16,5220.84
  region net S3: 5843.29,5881.17 5853.29,5881.07 5853.38,5879.93 5853.64,5878.8 5854.54,5876.59 5855.81,5874.52 5857.28,5872.67 5839.27,5872.76 5840.74,5874.6 5842.03,5876.68 5842.95,5878.9 5843.2,5880.03
  region net DOUT2: 4906.57,5589.96 4896.57,5589.96 4896.48,5591.09 4896.23,5592.23 4895.32,5594.44 4894.04,5596.52 4892.57,5598.36 4910.58,5598.36 4909.11,5596.52 4907.83,5594.44 4906.92,5592.23 4906.66,5591.09
  region net DOUT1: 4851.46,5526.96 4841.46,5526.96 4841.37,5528.1 4841.11,5529.23 4840.2,5531.45 4838.92,5533.52 4837.45,5535.37 4855.46,5535.37 4853.99,5533.52 4852.71,5531.45 4851.8,5529.23 4851.55,5528.1
  region net 3V3: 4729.25,5343.12 4739.25,5343.12 4739.34,5341.99 4739.6,5340.85 4740.5,5338.64 4741.79,5336.56 4743.26,5334.72 4725.24,5334.72 4726.72,5336.56 4728,5338.64 4728.91,5340.85 4729.16,5341.99
  region net 3V3: 4717.9,5321.78 4717.9,5331.78 4719.04,5331.87 4720.17,5332.12 4722.39,5333.03 4724.46,5334.31 4726.31,5335.78 4726.31,5317.77 4724.46,5319.24 4722.39,5320.52 4720.17,5321.43 4719.04,5321.69
  region net S1: 6085.55,5637.86 6095.55,5637.86 6095.64,5636.72 6095.9,5635.59 6096.8,5633.37 6098.09,5631.3 6099.56,5629.45 6081.55,5629.45 6083.02,5631.3 6084.3,5633.37 6085.21,5635.59 6085.46,5636.72
  region net S1: 6104.24,5607.77 6091.82,5606.04 6090.28,5607.4 6088.5,5608.72 6084.84,5610.95 6101.75,5617.16 6101.44,5616.01 6101.35,5614.78 6101.45,5613.49 6101.74,5612.2 6102.18,5610.95 6102.76,5609.76 6103.45,5608.69
  region net 3V3: 6912.32,5370.68 6922.32,5370.68 6922.41,5369.55 6922.67,5368.41 6923.58,5366.2 6924.86,5364.12 6926.33,5362.28 6908.32,5362.28 6909.79,5364.12 6911.07,5366.2 6911.98,5368.41 6912.23,5369.55
  region net EN: 6091.61,5281.06 6081.61,5281.06 6081.52,5282.19 6081.27,5283.33 6080.36,5285.54 6079.08,5287.62 6077.61,5289.46 6095.62,5289.46 6094.15,5287.62 6092.87,5285.54 6091.96,5283.33 6091.7,5282.19
  region net EN: 6081.61,5313.75 6091.61,5313.75 6091.7,5312.62 6091.96,5311.48 6092.87,5309.27 6094.15,5307.19 6095.62,5305.35 6077.61,5305.35 6079.08,5307.19 6080.36,5309.27 6081.27,5311.48 6081.52,5312.62
  region net EN: 6611.3,5369.48 6601.3,5369.48 6601.21,5370.62 6600.96,5371.75 6600.05,5373.97 6598.76,5376.04 6597.29,5377.89 6615.31,5377.89 6613.83,5376.04 6612.55,5373.97 6611.64,5371.75 6611.39,5370.62
  region net IO0: 5460.03,5703.67 5460.03,5713.67 5461.17,5713.76 5462.3,5714.01 5464.52,5714.92 5466.59,5716.2 5468.44,5717.67 5468.44,5699.66 5466.59,5701.13 5464.52,5702.41 5462.3,5703.32 5461.17,5703.58
  region net SIGNAL3: 4075.84,5440.99 4085.84,5440.99 4085.93,5439.86 4086.18,5438.72 4087.09,5436.51 4088.38,5434.43 4089.85,5432.59 4071.83,5432.59 4073.31,5434.43 4074.59,5436.51 4075.5,5438.72 4075.75,5439.86
  region net SIGNAL3: 4085.84,5408.3 4075.84,5408.3 4075.75,5409.43 4075.5,5410.57 4074.59,5412.78 4073.31,5414.86 4071.83,5416.7 4089.85,5416.7 4088.38,5414.86 4087.09,5412.78 4086.18,5410.57 4085.93,5409.43
  region net 3V3: 4282.4,5336.78 cw(c4277.4,5336.78) 4277.4,5331.78 4286.9,5326.78 4297.4,5331.78 cw(c4297.4,5336.78) 4292.4,5336.78
  region net 3V3: 6145.67,5535.38 ccw(c6145.67,5547.19) 6157.48,5547.19 6169.29,5525.61 6157.48,5499.95 ccw(c6145.67,5499.95) 6145.67,5511.76
Bottom Layer:
  region net 5V: 6276.59,5487.01 6276.59,5455.52 6273.42,5455.27 6270.12,5454.59 6266.76,5453.52 6263.42,5452.13 6260.17,5450.49 6257.1,5448.66 6254.28,5446.71 6251.78,5444.69 6251.78,5497.84 6254.28,5495.82 6257.1,5493.86 6260.17,5492.03 6263.42,5490.4 6266.76,5489.01 6270.12,5487.94 6273.42,5487.25
  region net RXD: 6180.11,5366.26 6180.11,5376.26 6182.94,5376.39 6185.35,5376.75 6187.4,5377.33 6189.14,5378.12 6190.62,5379.09 6191.9,5380.25 6193.02,5381.55 6194.04,5383.01 6198.17,5389.92 6199.48,5391.84 6201,5393.81 6202.8,5395.82 6204.91,5397.84 6204.91,5344.69 6202.8,5346.71 6201,5348.71 6199.48,5350.69 6198.17,5352.61 6194.04,5359.52 6193.02,5360.97 6191.9,5362.28 6190.62,5363.43 6189.14,5364.41 6187.4,5365.2 6185.35,5365.78 6182.94,5366.14
  region net TXD: 6180.11,5266.26 6180.11,5276.26 6182.94,5276.39 6185.35,5276.75 6187.4,5277.33 6189.14,5278.12 6190.62,5279.09 6191.9,5280.25 6193.02,5281.55 6194.04,5283.01 6198.17,5289.92 6199.48,5291.84 6201,5293.81 6202.8,5295.82 6204.91,5297.84 6204.91,5244.69 6202.8,5246.71 6201,5248.71 6199.48,5250.69 6198.17,5252.61 6194.04,5259.52 6193.02,5260.97 6191.9,5262.28 6190.62,5263.43 6189.14,5264.41 6187.4,5265.2 6185.35,5265.78 6182.94,5266.14
  region net 3V3: 5179.86,5067.43 5211.36,5067.43 ccw(c5227.1,5067.43) 5227.1,5051.68 5164.11,5051.68 ccw(c5164.11,5067.43)
  region net 3V3: 7357.99,5255.63 7357.99,5265.63 ccw(c7357.99,5270.63) 7362.99,5270.63 7362.99,5250.63 ccw(c7357.99,5250.63)
  region net SIGNAL1: 7367.78,5424.88 7360.71,5431.95 7362.49,5433.9 7363.85,5435.74 7364.83,5437.48 7365.47,5439.16 7365.82,5440.8 7365.92,5442.41 7365.82,5444.04 7365.55,5445.68 7363.8,5453.03 7363.13,5457.49 7362.99,5460 7363.06,5462.73 7398.55,5427.23 7395.83,5427.17 7393.32,5427.3 7388.86,5427.98 7381.51,5429.73 7379.86,5429.99 7378.24,5430.1 7376.62,5430 7374.99,5429.65 7373.31,5429.01 7371.56,5428.03 7369.73,5426.67
  region net S1: 7360.71,5589.31 7367.78,5596.39 7369.73,5594.6 7371.56,5593.24 7373.31,5592.26 7374.99,5591.62 7376.62,5591.27 7378.24,5591.17 7379.86,5591.27 7381.51,5591.54 7388.86,5593.29 7393.32,5593.97 7395.83,5594.1 7398.55,5594.03 7363.06,5558.54 7362.99,5561.26 7363.13,5563.77 7363.8,5568.23 7365.55,5575.58 7365.82,5577.23 7365.92,5578.85 7365.82,5580.47 7365.47,5582.11 7364.83,5583.78 7363.85,5585.53 7362.49,5587.36
  region net IO0: 6278.93,5727.29 6278.93,5737.29 6280.07,5737.38 6281.2,5737.63 6283.41,5738.54 6285.49,5739.82 6287.33,5741.29 6287.33,5723.28 6285.49,5724.75 6283.41,5726.04 6281.2,5726.94 6280.07,5727.2
  region net SIGNAL2: 6650.26,5500.15 6657.33,5507.23 6658.2,5506.48 6659.18,5505.86 6661.39,5504.94 6663.76,5504.38 6666.11,5504.11 6653.37,5491.38 6653.11,5493.72 6652.55,5496.1 6651.62,5498.3 6651,5499.29
  region net 3V3: 6037.18,5213.86 6037.18,5203.86 6035.39,5203.7 6033.83,5203.27 6032.45,5202.6 6031.19,5201.73 6028.79,5199.55 6026.16,5197.05 6026.16,5220.67 6028.79,5218.17 6031.19,5215.99 6032.45,5215.12 6033.83,5214.44 6035.39,5214.01
  region net S3: 5853.23,5848.42 5843.23,5848.42 5843.14,5849.56 5842.88,5850.7 5841.98,5852.91 5840.69,5854.98 5839.22,5856.83 5857.23,5856.83 5855.76,5854.98 5854.48,5852.91 5853.57,5850.7 5853.32,5849.56
  region net S3: 3810.37,5803.99 3803.3,5796.92 3802.43,5797.66 3801.45,5798.28 3799.24,5799.2 3796.87,5799.76 3794.52,5800.03 3807.26,5812.76 3807.52,5810.42 3808.08,5808.04 3809.01,5805.84 3809.63,5804.85
  region net DOUT1: 5999.39,5603.86 5999.39,5613.86 6000.53,5613.95 6001.67,5614.2 6003.88,5615.11 6005.95,5616.39 6007.8,5617.86 6007.8,5599.85 6005.95,5601.32 6003.88,5602.61 6001.67,5603.51 6000.53,5603.77
  region net DOUT2: 5999.39,5653.86 5999.39,5663.86 6000.53,5663.95 6001.67,5664.2 6003.88,5665.11 6005.95,5666.39 6007.8,5667.86 6007.8,5649.85 6005.95,5651.32 6003.88,5652.61 6001.67,5653.51 6000.53,5653.77
  region net DOUT2: 4909.6,5621.4 4916.67,5614.33 4915.93,5613.46 4915.31,5612.48 4914.38,5610.27 4913.82,5607.9 4913.56,5605.55 4900.82,5618.29 4903.17,5618.55 4905.54,5619.11 4907.75,5620.04 4908.73,5620.66
  region net DOUT1: 4862.8,5548.31 4862.8,5538.31 4861.67,5538.22 4860.53,5537.97 4858.32,5537.06 4856.24,5535.78 4854.4,5534.31 4854.4,5552.32 4856.24,5550.85 4858.32,5549.56 4860.53,5548.66 4861.67,5548.4
  region net 3V3: 5199.07,5197.9 5206.15,5204.97 5207.52,5203.81 5208.93,5203.02 5210.38,5202.52 5211.89,5202.24 5215.13,5202.09 5218.76,5202 5202.05,5185.29 5201.96,5188.92 5201.81,5192.16 5201.53,5193.67 5201.03,5195.12 5200.23,5196.53
  region net 3V3: 4750.6,5331.78 4750.6,5321.78 4749.46,5321.69 4748.33,5321.43 4746.11,5320.52 4744.04,5319.24 4742.19,5317.77 4742.19,5335.78 4744.04,5334.31 4746.11,5333.03 4748.33,5332.12 4749.46,5331.87
  region net 3V3: 5003.12,5321.78 5003.12,5331.78 5004.25,5331.87 5005.39,5332.12 5007.6,5333.03 5009.68,5334.31 5011.52,5335.78 5011.52,5317.77 5009.68,5319.24 5007.6,5320.52 5005.39,5321.43 5004.25,5321.69
  region net 3V3: 5035.81,5331.78 5035.81,5321.78 5034.68,5321.69 5033.54,5321.43 5031.33,5320.52 5029.25,5319.24 5027.41,5317.77 5027.41,5335.78 5029.25,5334.31 5031.33,5333.03 5033.54,5332.12 5034.68,5331.87
  region net RXD: 5347.06,5363.86 5347.06,5353.86 5345.93,5353.77 5344.79,5353.51 5342.58,5352.61 5340.5,5351.32 5338.66,5349.85 5338.66,5367.86 5340.5,5366.39 5342.58,5365.11 5344.79,5364.2 5345.93,5363.95
  region net TXD: 5347.06,5313.86 5347.06,5303.86 5345.93,5303.77 5344.79,5303.51 5342.58,5302.61 5340.5,5301.32 5338.66,5299.85 5338.66,5317.86 5340.5,5316.39 5342.58,5315.11 5344.79,5314.2 5345.93,5313.95
  region net SIGNAL2: 6023.77,5523.95 6030.84,5516.88 6030.1,5516.01 6029.48,5515.03 6028.55,5512.82 6027.99,5510.45 6027.73,5508.11 6014.99,5520.84 6017.34,5521.11 6019.71,5521.67 6021.92,5522.59 6022.9,5523.21
  region net 3V3: 6407.01,5671.05 6417.01,5671.05 6417.17,5669.26 6417.6,5667.7 6418.27,5666.32 6419.14,5665.06 6421.32,5662.65 6423.82,5660.03 6400.2,5660.03 6402.7,5662.65 6404.88,5665.06 6405.76,5666.32 6406.43,5667.7 6406.86,5669.26
  region net S1: 6106.9,5626.51 6106.9,5616.51 6105.76,5616.42 6104.63,5616.17 6102.41,5615.26 6100.34,5613.98 6098.49,5612.51 6098.49,5630.52 6100.34,5629.05 6102.41,5627.76 6104.63,5626.86 6105.76,5626.6
  region net SIGNAL1: 6030.84,5450.83 6023.77,5443.76 6022.9,5444.5 6021.92,5445.13 6019.71,5446.05 6017.34,5446.61 6014.99,5446.87 6027.73,5459.61 6027.99,5457.26 6028.55,5454.89 6029.48,5452.68 6030.1,5451.7
  region net 3V3: 6900.98,5349.33 6900.98,5359.33 6902.11,5359.42 6903.25,5359.68 6905.46,5360.59 6907.54,5361.87 6909.38,5363.34 6909.38,5345.33 6907.54,5346.8 6905.46,5348.08 6903.25,5348.99 6902.11,5349.24
  region net 3V3: 6922.32,5337.99 6912.32,5337.99 6912.23,5339.12 6911.98,5340.26 6911.07,5342.47 6909.79,5344.55 6908.32,5346.39 6926.33,5346.39 6924.86,5344.55 6923.58,5342.47 6922.67,5340.26 6922.41,5339.12
  region net EN: 6094.64,5312.5 6101.71,5305.43 6100.97,5304.56 6100.35,5303.58 6099.42,5301.37 6098.86,5299 6098.6,5296.65 6085.86,5309.39 6088.21,5309.65 6090.58,5310.21 6092.79,5311.14 6093.77,5311.76
  region net EN: 6589.95,5380.83 6589.95,5390.83 6591.09,5390.92 6592.22,5391.18 6594.44,5392.08 6596.51,5393.37 6598.36,5394.84 6598.36,5376.82 6596.51,5378.3 6594.44,5379.58 6592.22,5380.49 6591.09,5380.74
  region net IO0: 5484.4,5723.76 5491.47,5716.69 5490.73,5715.82 5490.11,5714.84 5489.19,5712.63 5488.63,5710.26 5488.36,5707.91 5475.63,5720.65 5477.97,5720.91 5480.34,5721.47 5482.55,5722.4 5483.53,5723.02
  region net SIGNAL3: 5999.39,5553.86 5999.39,5563.86 6000.53,5563.95 6001.67,5564.2 6003.88,5565.11 6005.95,5566.39 6007.8,5567.86 6007.8,5549.85 6005.95,5551.32 6003.88,5552.61 6001.67,5553.51 6000.53,5553.77
  region net SIGNAL3: 4097.19,5429.65 4097.19,5419.65 4096.05,5419.56 4094.92,5419.3 4092.7,5418.39 4090.63,5417.11 4088.78,5415.64 4088.78,5433.65 4090.63,5432.18 4092.7,5430.9 4094.92,5429.99 4096.05,5429.74
  region net 3V3: 5891.27,5975.32 5891.27,5985.32 5892.4,5985.41 5893.54,5985.66 5895.75,5986.57 5897.82,5987.85 5899.67,5989.33 5899.67,5971.31 5897.82,5972.78 5895.75,5974.07 5893.54,5974.97 5892.4,5975.23
  region net 3V3: 5912.61,5963.97 5902.61,5963.97 5902.52,5965.11 5902.27,5966.24 5901.36,5968.46 5900.08,5970.53 5898.61,5972.38 5916.62,5972.38 5915.15,5970.53 5913.86,5968.46 5912.96,5966.24 5912.7,5965.11
  region net 3V3: 5408.21,5985.32 5408.21,5975.32 5407.08,5975.23 5405.94,5974.97 5403.73,5974.07 5401.65,5972.78 5399.81,5971.31 5399.81,5989.33 5401.65,5987.85 5403.73,5986.57 5405.94,5985.66 5407.08,5985.41
  region net 3V3: 5190.24,5206.74 5194.58,5216.54 ccw(c5225.24,5247.2) 5214.43,5205.21 5202.06,5187.38 ccw(c5156.12,5172.62)
  region net 3V3: 6048.9,5213.86 6049.17,5203.86 ccw(c6049.17,5160.83) 6027.12,5197.78 6026.85,5219.83 ccw(c6048.9,5257.57)
  region net 3V3: 6407.01,5687.41 6417.01,5683.54 ccw(c6465.26,5683.54) 6422.34,5661.5 6400.99,5665.36 ccw(c6363.65,5687.41)

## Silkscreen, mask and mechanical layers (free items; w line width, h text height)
Top Silkscreen Layer:
  text "N极面向PCB" at 6854.33,5895.67 h78.74
  text "3V3 G 5V RX TX" at 6279.53,5712.6 h53.15 r270
  text "BOOT" at 6401.27,5361.88 h47.24
  text "RST" at 6646.62,5361.88 h47.24
  text "N极面向PCB" at 3704.72,5251.41 h78.74
  text "3V3 G Signal S1" at 7279.53,5216.54 h47.24 r90
  text "延音 地 持音 地 弱音 3V3" at 4629.92,5165.36 h51.18
  text "3V3 G Signal S1" at 6389.76,4803.15 h47.24 r90
  text "N极面向PCB" at 5357.99,4590.79 h78.74
Bottom Silkscreen Layer:
  text "Design By Ning / 2025/09/27" at 5933.07,5901.58 h78.74
Mechanical Layer:
  circle w1: c3625.98,5509.85 r39.37
  circle w1: c7326.77,5509.85 r39.37
  circle w1: c4177.17,5509.85 r39.37
  circle w1: c6775.59,5509.85 r39.37
  circle w1: c5279.53,4516.26 r39.37
  circle w1: c5830.71,4516.26 r39.37
  lines w1: 4492.13,5885.83 cw(c4492.13,5950.79) 4492.13,6015.75 4728.35,6015.75 cw(c4728.35,5950.79) 4728.35,5885.83 4492.13,5885.83 ; 4659.48,4813 4659.53,4813 4659.53,4866.15 5233.82,4866.15 5233.82,4813 4659.48,4813 ; 4757.6,4014.3 4993.82,4014.3 ccw(c4993.82,4079.26) 4993.82,4144.22 4757.6,4144.22 ccw(c4757.6,4079.26) 4757.6,4014.3 ; 6115.87,4014.3 cw(c6115.87,4079.26) 6115.87,4144.22 6352.09,4144.22 cw(c6352.09,4079.26) 6352.09,4014.3 6115.87,4014.3 ; 6165.35,5885.83 cw(c6165.35,5950.79) 6165.35,6015.75 6401.57,6015.75 cw(c6401.57,5950.79) 6401.57,5885.83 6165.35,5885.83
Mech6:
  lines w3.94: 3507.87,5509.85 7444.88,5509.85 ; 3507.87,5935.04 7444.88,5935.04 ; 3901.57,5214.57 3901.57,6061.03 ; 4492.13,5935.04 4728.35,5935.04 ; 4609.96,4091.07 6499.72,4091.07 ; 4609.96,4516.26 6499.72,4516.26 ; 4610.24,5214.57 4610.24,6061.03 ; 4757.6,4091.07 4993.82,4091.07 ; 4875.71,3965.08 4875.71,4811.54 ; 5476.38,5214.57 5476.38,6061.03 ; 5554.84,3965.08 5554.84,4811.54 ; 6115.87,4091.07 6352.09,4091.07 ; 6165.35,5935.04 6401.57,5935.04 ; 6233.98,3965.08 6233.98,4811.54 ; 6283.46,5214.57 6283.46,6061.03 ; 7051.18,5214.57 7051.18,6061.03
